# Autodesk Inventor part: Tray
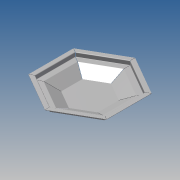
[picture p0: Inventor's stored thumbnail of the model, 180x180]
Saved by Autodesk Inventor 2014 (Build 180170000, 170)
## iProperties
Created: 2013-06
Part Number: Tray
Material: Steel, Mild
Document SubType Name: Sheet Metal
Designer: 1103005
Density: 1 g/cm^3
Flat Pattern Width: 55.3697 cm
Flat Pattern Length: 61.9397 cm
Flat Pattern Area: 3429.58 cm^2
Sheet Metal Rule: Default_mm
Sheet Metal Width: 553.697 mm
Sheet Metal Length: 619.397 mm
Sheet Metal Area: 342958.024 mm^2
Appearance: Steel
Author: 1103005
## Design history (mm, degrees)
node "Face1"
  sketch "Sketch1"
    geometry: L1 (-115, 66.395)-(0, 132.791); L2 (0, 132.791)-(115, 66.395); L3 (115, 66.395)-(115, -66.395); L4 (115, -66.395)-(0, -132.791); L5 (0, -132.791)-(-115, -66.395); L6 (-115, -66.395)-(-115, 66.395); 2 further points
    constraints: 12 end point, 1 coincident, 1 vertical, 13 other
    dimensions: "d0" = 230 distance between parallel lines of L3 L6
node "Contour Flange1"
  sketch "Sketch2"
    geometry: L1 (0, 0)-(-115, 0); L2 (-115, 0)-(-184.282, 40); L3 (-184.282, 40)-(-219.282, 40); L4 (-219.282, 40)-(-219.282, 65); L5 (-219.282, 65)-(-244.282, 65)
    constraints: 10 end point, 2 horizontal, 1 parallel, 1 perpendicular
    dimensions: "d2" = 115 distance of L1.start L1.end; "d3" = 25 distance of L4.end L5.end; "d4" = 25 distance of L3.end L4.end; "d5" = 35 distance of L2.end L3.end; "d7" = 150 deg angle of L2 L3; "d8" = 40 distance between parallel lines of L1 L3
body "Solid1"
face "Plate1" dims "Thickness" = 2
face "Plate2" dims "d9" = 2 (= BendReliefWidth), "d10" = 1 (= BendReliefDepth), "d11" = 4 (= MinimumRemnant), "d12" = 2 (= BendRadius), "d13" = 2 (= BendRadius), "d14" = 1.2, "d15" = 8 (= CornerReliefSize), "d16" = 2 (= GapSize), "d17" = 2 (= JacobiRadiusSize), "SeamGap" = 0.01, "Thickness" = 2
bend "Bend1" dims "d9" = 2 (= BendReliefWidth), "d10" = 1 (= BendReliefDepth), "d11" = 4 (= MinimumRemnant), "d12" = 2 (= BendRadius), "d13" = 2 (= BendRadius), "d14" = 1.2, "SeamGap" = 0.01, "Thickness" = 2
feature "Corner1" dims "d14" = 1.2, "d15" = 8 (= CornerReliefSize), "d16" = 2 (= GapSize), "d17" = 2 (= JacobiRadiusSize)
feature "Definition1"
other parameters: "BendRadius" = 2 (= Thickness), "BendReliefWidth" = 2 (= Thickness), "BendReliefDepth" = 1 (= 0.5 x Thickness), "CornerReliefSize" = 8 (= 4 x Thickness), "MinimumRemnant" = 4 (= 2 x Thickness), "TransitionRadius" = 2 (= BendRadius), "JacobiRadiusSize" = 2 (= BendRadius), "GapSize" = 2 (= Thickness), "d1" = 2 (= BendRadius), "BendRadius" = 2, "BendReliefDepth" = 1, "BendReliefWidth" = 2, "CornerReliefSize" = 8, "GapSize" = 2, "JacobiRadiusSize" = 2, "MinimumRemnant" = 4, "Thickness" = 2, "TransitionRadius" = 2
